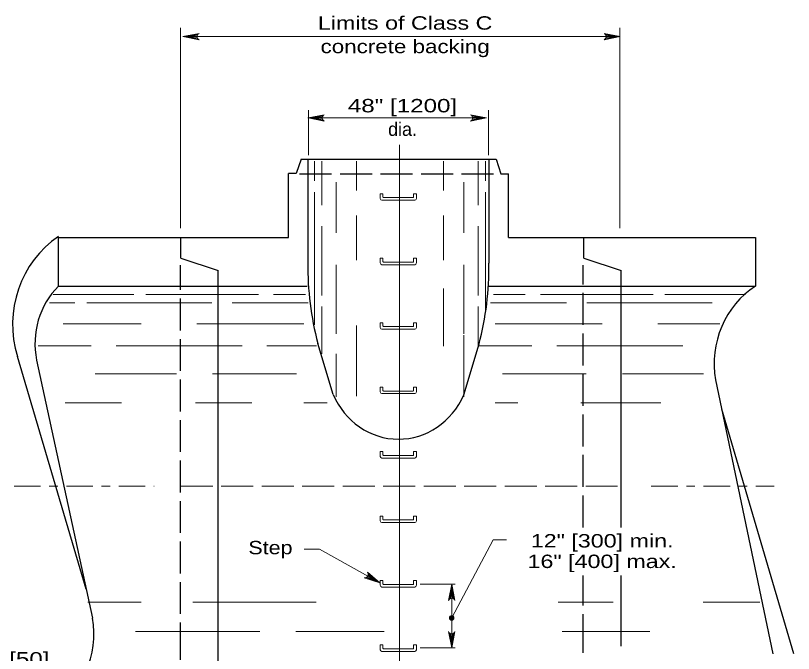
# Model space of a CAD drawing. Extents: x 1170.6 to 1204.6, y 975 to 1019.
# Drawn here: x 1175.39 to 1184.45, y 1000.96 to 1008.4 of the extents above; entities that cross this region are included whole.
import ezdxf
from ezdxf.enums import TextEntityAlignment as Align

# ---------------------------------------------------------------- set-up
doc = ezdxf.new("R2010")
doc.units = 0
doc.header["$LTSCALE"] = 0.062
doc.linetypes.add('DOT_DASHED', pattern=[7.7, 5, -1.2, 0.3, -1.2])
doc.linetypes.add('LONG_DASHED', pattern=[7.5, 6, -1.5])
doc.layers.add('1', color=7, linetype='Continuous', lineweight=13)

msp = doc.modelspace()

# ---------------------------------------------------------------- hatches: boundary and pattern name
at = {"layer": '1'}
msp.add_hatch(color=256, dxfattribs=at).paths.add_polyline_path([(1180.49779, 1001.37637, 1), (1180.44436, 1001.37637, 1)])

# ---------------------------------------------------------------- linework, layer by layer
for p, q in [((1177.30833, 1005.91808), (1177.30833, 1008.25417)), ((1177.50883, 1008.1745), (1177.33917, 1008.15075)), ((1182.26492, 1008.1745), (1182.43458, 1008.15075)), ((1182.43183, 1005.91808), (1182.43183, 1008.25417)), ((1177.50308, 1008.16275), (1177.33917, 1008.15075)), ((1177.33917, 1008.15075), (1182.43458, 1008.15075)), ((1177.50133, 1008.15075), (1177.33917, 1008.15075)), ((1177.50433, 1008.1355), (1177.33917, 1008.15075)), ((1177.51083, 1008.1245), (1177.33917, 1008.15075)), ((1182.26292, 1008.1245), (1182.43458, 1008.15075)), ((1182.26942, 1008.1355), (1182.43458, 1008.15075)), ((1182.27067, 1008.16275), (1182.43458, 1008.15075)), ((1182.27242, 1008.15075), (1182.43458, 1008.15075)), ((1178.80183, 1006.76825), (1178.80183, 1007.29333)), ((1180.89992, 1006.76825), (1180.89992, 1007.29333)), ((1180.89992, 1006.76825), (1180.89992, 1007.29333)), ((1178.79275, 1007.20317), (1180.878, 1007.20317)), ((1178.96883, 1007.22692), (1178.79917, 1007.20317)), ((1178.96308, 1007.21517), (1178.79917, 1007.20317)), ((1178.96133, 1007.20317), (1178.79917, 1007.20317)), ((1178.96433, 1007.188), (1178.79917, 1007.20317)), ((1178.97083, 1007.177), (1178.79917, 1007.20317)), ((1180.70633, 1007.177), (1180.878, 1007.20317)), ((1180.70833, 1007.22692), (1180.878, 1007.20317)), ((1180.71283, 1007.188), (1180.878, 1007.20317)), ((1180.71408, 1007.21517), (1180.878, 1007.20317)), ((1180.71583, 1007.20317), (1180.878, 1007.20317)), ((1179.86242, 1005.99008), (1179.86242, 1006.88858)), ((1178.87175, 1006.46967), (1178.87175, 1006.69792)), ((1178.95575, 1006.18633), (1178.95575, 1006.69792)), ((1179.36083, 1006.35633), (1179.36083, 1006.69792)), ((1180.37458, 1006.35633), (1180.37458, 1006.69792)), ((1180.77967, 1006.18633), (1180.77967, 1006.69792)), ((1180.86375, 1006.46967), (1180.86375, 1006.69792)), ((1179.12392, 1005.86258), (1179.12392, 1006.45342)), ((1180.6115, 1005.86258), (1180.6115, 1006.45342)), ((1178.87175, 1004.79408), (1178.87175, 1006.34017)), ((1179.63633, 1006.31975), (1179.63633, 1006.26408)), ((1179.63633, 1006.31975), (1179.67017, 1006.31975)), ((1179.63633, 1006.31975), (1179.63633, 1006.26408)), ((1179.63633, 1006.31975), (1179.67017, 1006.31975)), ((1179.67033, 1006.31975), (1179.67033, 1006.28108)), ((1179.67033, 1006.31975), (1179.67033, 1006.28108)), ((1179.84867, 1006.27467), (1179.67683, 1006.27467)), ((1179.84867, 1006.27467), (1179.67683, 1006.27467)), ((1179.84867, 1006.27467), (1180.0205, 1006.27467)), ((1179.84867, 1006.27467), (1180.0205, 1006.27467)), ((1180.027, 1006.31975), (1180.027, 1006.28108)), ((1180.027, 1006.31975), (1180.027, 1006.28108)), ((1180.06092, 1006.31975), (1180.02717, 1006.31975)), ((1180.06092, 1006.31975), (1180.02717, 1006.31975)), ((1180.06092, 1006.31975), (1180.06092, 1006.26408)), ((1180.06092, 1006.31975), (1180.06092, 1006.26408)), ((1180.86375, 1004.94383), (1180.86375, 1006.34017)), ((1179.84867, 1006.24375), (1179.65758, 1006.24375)), ((1179.84867, 1006.24375), (1179.65758, 1006.24375)), ((1179.84867, 1006.24375), (1180.03967, 1006.24375)), ((1179.84867, 1006.24375), (1180.03967, 1006.24375)), ((1179.36083, 1005.54683), (1179.36083, 1006.065)), ((1179.86242, 1000.46425), (1179.86242, 1006.03058)), ((1180.37458, 1005.54683), (1180.37458, 1006.065)), ((1181.13325, 1005.817), (1181.13325, 1006.03058)), ((1178.95575, 1005.134), (1178.95575, 1005.9435)), ((1180.77967, 1005.134), (1180.77967, 1005.9435)), ((1179.63633, 1005.5685), (1179.63633, 1005.51283)), ((1179.63633, 1005.5685), (1179.67017, 1005.5685)), ((1179.63633, 1005.5685), (1179.63633, 1005.51283)), ((1179.63633, 1005.5685), (1179.67017, 1005.5685)), ((1179.67033, 1005.5685), (1179.67033, 1005.52983)), ((1179.67033, 1005.5685), (1179.67033, 1005.52983)), ((1180.027, 1005.5685), (1180.027, 1005.52983)), ((1180.027, 1005.5685), (1180.027, 1005.52983)), ((1180.06092, 1005.5685), (1180.02717, 1005.5685)), ((1180.06092, 1005.5685), (1180.02717, 1005.5685)), ((1180.06092, 1005.5685), (1180.06092, 1005.51283)), ((1180.06092, 1005.5685), (1180.06092, 1005.51283)), ((1179.12392, 1004.68883), (1179.12392, 1005.49025)), ((1179.84867, 1005.4925), (1179.65758, 1005.4925)), ((1179.84867, 1005.4925), (1179.65758, 1005.4925)), ((1179.84867, 1005.52342), (1179.67683, 1005.52342)), ((1179.84867, 1005.52342), (1179.67683, 1005.52342)), ((1179.84867, 1005.52342), (1180.0205, 1005.52342)), ((1179.84867, 1005.52342), (1180.0205, 1005.52342)), ((1179.84867, 1005.4925), (1180.03967, 1005.4925)), ((1179.84867, 1005.4925), (1180.03967, 1005.4925)), ((1180.6115, 1004.68883), (1180.6115, 1005.49025)), ((1180.37458, 1004.54317), (1180.37458, 1005.21492)), ((1175.82733, 1005.14475), (1176.76683, 1005.14475)), ((1176.90442, 1005.14475), (1178.21883, 1005.14475)), ((1178.39467, 1005.14475), (1178.76525, 1005.14475)), ((1181.32925, 1005.14475), (1180.95867, 1005.14475)), ((1182.81958, 1005.14475), (1181.50508, 1005.14475)), ((1183.89658, 1005.14475), (1182.95717, 1005.14475)), ((1175.78142, 1005.04767), (1176.079, 1005.04767)), ((1176.2165, 1005.04767), (1177.67625, 1005.04767)), ((1177.91317, 1005.04767), (1178.79967, 1005.04767)), ((1178.95575, 1004.45408), (1178.95575, 1005.00458)), ((1180.77967, 1004.52692), (1180.77967, 1005.00458)), ((1181.81075, 1005.04767), (1180.92425, 1005.04767)), ((1183.50742, 1005.04767), (1182.04767, 1005.04767)), ((1179.63633, 1004.81725), (1179.63633, 1004.76158)), ((1179.63633, 1004.81725), (1179.67017, 1004.81725)), ((1179.63633, 1004.81725), (1179.63633, 1004.76158)), ((1179.63633, 1004.81725), (1179.67017, 1004.81725)), ((1179.67033, 1004.81725), (1179.67033, 1004.77858)), ((1179.67033, 1004.81725), (1179.67033, 1004.77858)), ((1180.027, 1004.81725), (1180.027, 1004.77858)), ((1180.027, 1004.81725), (1180.027, 1004.77858)), ((1180.06092, 1004.81725), (1180.02717, 1004.81725)), ((1180.06092, 1004.81725), (1180.02717, 1004.81725)), ((1180.06092, 1004.81725), (1180.06092, 1004.76158)), ((1180.06092, 1004.81725), (1180.06092, 1004.76158)), ((1175.94142, 1004.80483), (1176.85092, 1004.80483)), ((1177.50042, 1004.80483), (1178.74617, 1004.80483)), ((1179.36083, 1003.96033), (1179.36083, 1004.786)), ((1179.84867, 1004.74125), (1179.65758, 1004.74125)), ((1179.84867, 1004.74125), (1179.65758, 1004.74125)), ((1179.84867, 1004.77217), (1179.67683, 1004.77217)), ((1179.84867, 1004.77217), (1179.67683, 1004.77217)), ((1179.84867, 1004.77217), (1180.0205, 1004.77217)), ((1179.84867, 1004.77217), (1180.0205, 1004.77217)), ((1179.84867, 1004.74125), (1180.03967, 1004.74125)), ((1179.84867, 1004.74125), (1180.03967, 1004.74125)), ((1182.2235, 1004.80483), (1180.97783, 1004.80483)), ((1183.59525, 1004.80483), (1182.873, 1004.80483)), ((1180.6115, 1003.95225), (1180.6115, 1004.67267)), ((1175.6515, 1004.54592), (1176.27008, 1004.54592)), ((1176.5605, 1004.54592), (1178.02783, 1004.54592)), ((1178.31825, 1004.54592), (1178.897, 1004.54592)), ((1181.40575, 1004.54592), (1180.78667, 1004.54592)), ((1183.16342, 1004.54592), (1181.69617, 1004.54592)), ((1179.12392, 1003.95225), (1179.12392, 1004.45408)), ((1176.31592, 1004.222), (1177.26358, 1004.222)), ((1177.68392, 1004.222), (1178.66208, 1004.222)), ((1182.04, 1004.222), (1181.06183, 1004.222)), ((1183.40808, 1004.222), (1182.46033, 1004.222)), ((1179.63633, 1004.06608), (1179.63633, 1004.01033)), ((1179.63633, 1004.06608), (1179.67017, 1004.06608)), ((1179.63633, 1004.06608), (1179.63633, 1004.01033)), ((1179.63633, 1004.06608), (1179.67017, 1004.06608)), ((1179.67033, 1004.06608), (1179.67033, 1004.02733)), ((1179.67033, 1004.06608), (1179.67033, 1004.02733)), ((1179.84867, 1004.02092), (1179.67683, 1004.02092)), ((1179.84867, 1004.02092), (1179.67683, 1004.02092)), ((1179.84867, 1004.02092), (1180.0205, 1004.02092)), ((1179.84867, 1004.02092), (1180.0205, 1004.02092)), ((1180.027, 1004.06608), (1180.027, 1004.02733)), ((1180.027, 1004.06608), (1180.027, 1004.02733)), ((1180.06092, 1004.06608), (1180.02717, 1004.06608)), ((1180.06092, 1004.06608), (1180.02717, 1004.06608)), ((1180.06092, 1004.06608), (1180.06092, 1004.01033)), ((1180.06092, 1004.06608), (1180.06092, 1004.01033)), ((1179.84867, 1003.99), (1179.65758, 1003.99)), ((1179.84867, 1003.99), (1179.65758, 1003.99)), ((1179.84867, 1003.99), (1180.03967, 1003.99)), ((1179.84867, 1003.99), (1180.03967, 1003.99)), ((1175.96433, 1003.882), (1176.62167, 1003.882)), ((1177.48517, 1003.882), (1178.1425, 1003.882)), ((1178.74625, 1003.882), (1179.02133, 1003.882)), ((1180.97775, 1003.882), (1181.24325, 1003.882)), ((1182.90933, 1003.882), (1181.977, 1003.882)), ((1179.63633, 1003.31483), (1179.63633, 1003.25908)), ((1179.63633, 1003.31483), (1179.67017, 1003.31483)), ((1179.63633, 1003.31483), (1179.63633, 1003.25908)), ((1179.63633, 1003.31483), (1179.67017, 1003.31483)), ((1179.67033, 1003.31483), (1179.67033, 1003.27608)), ((1179.67033, 1003.31483), (1179.67033, 1003.27608)), ((1179.84867, 1003.26967), (1179.67683, 1003.26967)), ((1179.84867, 1003.26967), (1179.67683, 1003.26967)), ((1179.84867, 1003.26967), (1180.0205, 1003.26967)), ((1179.84867, 1003.26967), (1180.0205, 1003.26967)), ((1180.027, 1003.31483), (1180.027, 1003.27608)), ((1180.027, 1003.31483), (1180.027, 1003.27608)), ((1180.06092, 1003.31483), (1180.02717, 1003.31483)), ((1180.06092, 1003.31483), (1180.02717, 1003.31483)), ((1180.06092, 1003.31483), (1180.06092, 1003.25908)), ((1180.06092, 1003.31483), (1180.06092, 1003.25908)), ((1179.84867, 1003.23883), (1179.65758, 1003.23883)), ((1179.84867, 1003.23883), (1179.65758, 1003.23883)), ((1179.84867, 1003.23883), (1180.03967, 1003.23883)), ((1179.84867, 1003.23883), (1180.03967, 1003.23883)), ((1179.63633, 1002.56358), (1179.63633, 1002.50783)), ((1179.63633, 1002.56358), (1179.67017, 1002.56358)), ((1179.63633, 1002.56358), (1179.63633, 1002.50783)), ((1179.63633, 1002.56358), (1179.67017, 1002.56358)), ((1179.67033, 1002.56358), (1179.67033, 1002.52483)), ((1179.67033, 1002.56358), (1179.67033, 1002.52483)), ((1180.027, 1002.56358), (1180.027, 1002.52483)), ((1180.027, 1002.56358), (1180.027, 1002.52483)), ((1180.06092, 1002.56358), (1180.02717, 1002.56358)), ((1180.06092, 1002.56358), (1180.02717, 1002.56358)), ((1180.06092, 1002.56358), (1180.06092, 1002.50783)), ((1180.06092, 1002.56358), (1180.06092, 1002.50783)), ((1179.84867, 1002.48758), (1179.65758, 1002.48758)), ((1179.84867, 1002.48758), (1179.65758, 1002.48758)), ((1179.84867, 1002.51842), (1179.67683, 1002.51842)), ((1179.84867, 1002.51842), (1179.67683, 1002.51842)), ((1179.84867, 1002.51842), (1180.0205, 1002.51842)), ((1179.84867, 1002.51842), (1180.0205, 1002.51842)), ((1179.84867, 1002.48758), (1180.03967, 1002.48758)), ((1179.84867, 1002.48758), (1180.03967, 1002.48758)), ((1179.47408, 1001.84858), (1179.6335, 1001.78592)), ((1179.48483, 1001.856), (1179.6335, 1001.78592)), ((1179.49225, 1001.86558), (1179.6335, 1001.78592)), ((1179.49692, 1001.89308), (1179.6335, 1001.78592)), ((1179.49717, 1001.88033), (1179.6335, 1001.78592)), ((1179.63633, 1001.81233), (1179.63633, 1001.75658)), ((1179.63633, 1001.81233), (1179.67017, 1001.81233)), ((1179.63633, 1001.81233), (1179.63633, 1001.75658)), ((1179.63633, 1001.81233), (1179.67017, 1001.81233)), ((1179.84867, 1001.73633), (1179.65758, 1001.73633)), ((1179.84867, 1001.73633), (1179.65758, 1001.73633)), ((1179.67033, 1001.81233), (1179.67033, 1001.77358)), ((1179.67033, 1001.81233), (1179.67033, 1001.77358)), ((1179.84867, 1001.76717), (1179.67683, 1001.76717)), ((1179.84867, 1001.76717), (1179.67683, 1001.76717)), ((1179.84867, 1001.76717), (1180.0205, 1001.76717)), ((1179.84867, 1001.76717), (1180.0205, 1001.76717)), ((1179.84867, 1001.73633), (1180.03967, 1001.73633)), ((1179.84867, 1001.73633), (1180.03967, 1001.73633)), ((1180.027, 1001.81233), (1180.027, 1001.77358)), ((1180.027, 1001.81233), (1180.027, 1001.77358)), ((1180.06092, 1001.81233), (1180.02717, 1001.81233)), ((1180.06092, 1001.81233), (1180.02717, 1001.81233)), ((1180.06092, 1001.81233), (1180.06092, 1001.75658)), ((1180.06092, 1001.81233), (1180.06092, 1001.75658)), ((1180.10492, 1001.76967), (1180.51083, 1001.76967)), ((1180.44483, 1001.59658), (1180.47108, 1001.76825)), ((1180.45583, 1001.60308), (1180.47108, 1001.76825)), ((1180.47108, 1001.029), (1180.47108, 1001.76825)), ((1180.47108, 1001.029), (1180.47108, 1001.76825)), ((1180.47108, 1001.60608), (1180.47108, 1001.76825)), ((1180.48308, 1001.60433), (1180.47108, 1001.76825)), ((1180.49483, 1001.59858), (1180.47108, 1001.76825)), ((1176.85158, 1001.56), (1176.23158, 1001.56)), ((1178.89183, 1001.56), (1177.45225, 1001.56)), ((1182.35258, 1001.56), (1181.71383, 1001.56)), ((1184.06458, 1001.56), (1183.40133, 1001.56)), ((1176.78483, 1001.21992), (1178.234, 1001.21992)), ((1178.65342, 1001.21992), (1179.68317, 1001.21992)), ((1180.44733, 1001.19858), (1180.47108, 1001.029)), ((1180.45908, 1001.19283), (1180.47108, 1001.029)), ((1180.49733, 1001.20058), (1180.47108, 1001.029)), ((1180.48633, 1001.19408), (1180.47108, 1001.029)), ((1180.47108, 1001.19117), (1180.47108, 1001.029)), ((1181.757, 1001.21992), (1182.78158, 1001.21992)), ((1179.63633, 1001.06108), (1179.63633, 1001.00533)), ((1179.63633, 1001.06108), (1179.67017, 1001.06108)), ((1179.63633, 1001.06108), (1179.63633, 1001.00533)), ((1179.63633, 1001.06108), (1179.67017, 1001.06108)), ((1179.67033, 1001.06108), (1179.67033, 1001.02233)), ((1179.67033, 1001.06108), (1179.67033, 1001.02233)), ((1179.84867, 1001.01592), (1179.67683, 1001.01592)), ((1179.84867, 1001.01592), (1179.67683, 1001.01592)), ((1179.84867, 1001.01592), (1180.0205, 1001.01592)), ((1179.84867, 1001.01592), (1180.0205, 1001.01592)), ((1180.027, 1001.06108), (1180.027, 1001.02233)), ((1180.027, 1001.06108), (1180.027, 1001.02233)), ((1180.06092, 1001.06108), (1180.02717, 1001.06108)), ((1180.06092, 1001.06108), (1180.02717, 1001.06108)), ((1180.06092, 1001.06108), (1180.06092, 1001.00533)), ((1180.06092, 1001.06108), (1180.06092, 1001.00533)), ((1180.10275, 1001.02683), (1180.51083, 1001.02683)), ((1179.84867, 1000.98508), (1179.65758, 1000.98508)), ((1179.84867, 1000.98508), (1179.65758, 1000.98508)), ((1179.84867, 1000.98508), (1180.03967, 1000.98508)), ((1179.84867, 1000.98508), (1180.03967, 1000.98508))]:
    msp.add_line(p, q, dxfattribs=at)
at = {"layer": '1', "lineweight": 25}
for p, q in [((1178.71667, 1006.7225), (1178.65942, 1006.5545)), ((1178.79575, 1006.71942), (1178.79575, 1006.01433)), ((1180.90442, 1006.71942), (1180.90442, 1005.96583)), ((1178.65958, 1006.55425), (1178.57008, 1006.55425)), ((1178.57008, 1005.80992), (1178.57008, 1006.55425)), ((1181.04267, 1006.55333), (1181.13325, 1006.55333)), ((1181.13325, 1005.80992), (1181.13325, 1006.55333)), ((1178.57008, 1005.81792), (1178.57008, 1006.03058)), ((1178.79575, 1006.03058), (1178.79575, 1005.51475)), ((1180.90442, 1006.03058), (1180.90442, 1005.509)), ((1175.88767, 1005.24283), (1175.88767, 1005.80992)), ((1175.88767, 1005.80992), (1178.57008, 1005.80992)), ((1181.13325, 1005.80992), (1184.01167, 1005.80992)), ((1184.01167, 1005.80992), (1184.01167, 1005.24283)), ((1177.3145, 1005.57092), (1177.3145, 1005.8045)), ((1182.00983, 1005.57092), (1182.00983, 1005.8045)), ((1177.3145, 1005.57092), (1177.75008, 1005.42475)), ((1182.00983, 1005.57092), (1182.44542, 1005.42475)), ((1182.44542, 1002.43117), (1182.44542, 1005.42475)), ((1175.88767, 1005.24283), (1178.78625, 1005.24283)), ((1180.8935, 1005.24283), (1184.01167, 1005.24283)), ((1179.08892, 1003.98075), (1178.91033, 1004.5745)), ((1180.61125, 1003.97508), (1180.78983, 1004.56883)), ((1176.2115, 1001.7115), (1175.40958, 1004.42192)), ((1175.6325, 1004.38142), (1176.2845, 1001.37525)), ((1183.545, 1004.14933), (1184.21617, 1000.9575)), ((1183.61792, 1003.81308), (1184.45458, 1000.9625)), ((1182.44542, 1001.04808), (1182.44542, 1001.87108))]:
    msp.add_line(p, q, dxfattribs=at)
at = {"layer": '1', "linetype": 'LONG_DASHED', "lineweight": 25}
for p, q in [((1178.69883, 1006.55358), (1181.00992, 1006.55358)), ((1182.004, 1002.43117), (1182.004, 1005.486)), ((1182.004, 1001.04808), (1182.004, 1001.87108)), ((1182.004, 1000.96917), (1182.004, 1001.04808))]:
    msp.add_line(p, q, dxfattribs=at)
at = {"layer": '1', "linetype": 'DOT_DASHED'}
for p, q in [((1174.75975, 1002.91058), (1177.00483, 1002.91058)), ((1182.79675, 1002.91058), (1184.23067, 1002.91058))]:
    msp.add_line(p, q, dxfattribs=at)
at = {"layer": '1', "linetype": 'LONG_DASHED'}
msp.add_line((1177.31367, 1002.91058), (1182.42, 1002.91058), dxfattribs=at)
at = {"layer": '1'}
for points in [[(1177.52658, 1008.11325), (1177.33917, 1008.15075), (1177.52658, 1008.18825)], [(1182.24717, 1008.11325), (1182.43458, 1008.15075), (1182.24717, 1008.18825)], [(1178.98658, 1007.16575), (1178.79917, 1007.20317), (1178.98658, 1007.24067)], [(1180.69058, 1007.16575), (1180.878, 1007.20317), (1180.69058, 1007.24067)], [(1181.11058, 1002.28567), (1180.95542, 1002.28567), (1180.47108, 1001.37633)], [(1179.6335, 1001.78592), (1178.93092, 1002.17842), (1178.7525, 1002.17842)], [(1179.48867, 1001.91058), (1179.6335, 1001.78592), (1179.45192, 1001.84533)], [(1180.43358, 1001.58083), (1180.47108, 1001.76825), (1180.50858, 1001.58083)], [(1180.50858, 1001.21633), (1180.47108, 1001.029), (1180.43358, 1001.21633)]]:
    msp.add_lwpolyline(points, dxfattribs=at)
at = {"layer": '1', "lineweight": 25}
for points in [[(1178.71667, 1006.7225), (1180.98933, 1006.7225), (1181.04267, 1006.55333)], [(1177.75008, 1000.081), (1177.75008, 1000.951), (1177.75008, 1005.42475)]]:
    msp.add_lwpolyline(points, dxfattribs=at)
at = {"layer": '1', "linetype": 'LONG_DASHED', "lineweight": 25}
msp.add_lwpolyline([(1177.30867, 999.94333), (1177.30867, 1000.951), (1177.30867, 1005.486)], dxfattribs=at)
at = {"layer": '1'}
msp.add_circle((1180.47107, 1001.37637), 0.02671, dxfattribs=at)
for centre, start, end in [((1177.54173, 1008.15078), 112.08782, 247.91395), ((1182.23202, 1008.15078), 292.08605, 67.91218), ((1179.00171, 1007.20324), 112.08782, 247.91395), ((1180.67544, 1007.20324), 292.08605, 67.91218), ((1179.45708, 1001.88536), 262.67925, 38.50537), ((1180.47112, 1001.5657), 22.08782, 157.91395), ((1180.47103, 1001.2315), 202.08782, 337.91395)]:
    msp.add_arc(centre, 0.04045, start, end, dxfattribs=at)
for centre, major_axis, start_param, end_param in [((1179.6581, 1006.26695), (0, -0.0232), 4.8374934, 6.2601456), ((1179.6581, 1006.26695), (0, -0.0232), 4.8374934, 6.2601456), ((1179.67645, 1006.2811), (0, -0.00648), 4.7166392, 6.345136), ((1179.67645, 1006.2811), (0, -0.00648), 4.7166392, 6.345136), ((1180.02084, 1006.2811), (0, -0.00648), 6.2212346, 7.8497314), ((1180.02084, 1006.2811), (0, -0.00648), 6.2212346, 7.8497314), ((1180.0392, 1006.26695), (0, -0.0232), 0.0230398, 1.4456919), ((1180.0392, 1006.26695), (0, -0.0232), 0.0230398, 1.4456919), ((1179.6581, 1005.5157), (0, -0.0232), 4.8374934, 6.2601456), ((1179.6581, 1005.5157), (0, -0.0232), 4.8374934, 6.2601456), ((1179.67645, 1005.52985), (0, -0.00648), 4.7166392, 6.345136), ((1179.67645, 1005.52985), (0, -0.00648), 4.7166392, 6.345136), ((1180.02084, 1005.52985), (0, -0.00648), 6.2212346, 7.8497314), ((1180.02084, 1005.52985), (0, -0.00648), 6.2212346, 7.8497314), ((1180.0392, 1005.5157), (0, -0.0232), 0.0230398, 1.4456919), ((1180.0392, 1005.5157), (0, -0.0232), 0.0230398, 1.4456919), ((1179.6581, 1004.76446), (0, -0.0232), 4.8374934, 6.2601456), ((1179.6581, 1004.76446), (0, -0.0232), 4.8374934, 6.2601456), ((1179.67645, 1004.77861), (0, -0.00648), 4.7166392, 6.345136), ((1179.67645, 1004.77861), (0, -0.00648), 4.7166392, 6.345136), ((1180.02084, 1004.77861), (0, -0.00648), 6.2212346, 7.8497314), ((1180.02084, 1004.77861), (0, -0.00648), 6.2212346, 7.8497314), ((1180.0392, 1004.76446), (0, -0.0232), 0.0230398, 1.4456919), ((1180.0392, 1004.76446), (0, -0.0232), 0.0230398, 1.4456919), ((1179.6581, 1004.01321), (0, -0.0232), 4.8374934, 6.2601456), ((1179.6581, 1004.01321), (0, -0.0232), 4.8374934, 6.2601456), ((1179.67645, 1004.02736), (0, -0.00648), 4.7166392, 6.345136), ((1179.67645, 1004.02736), (0, -0.00648), 4.7166392, 6.345136), ((1180.02084, 1004.02736), (0, -0.00648), 6.2212346, 7.8497314), ((1180.02084, 1004.02736), (0, -0.00648), 6.2212346, 7.8497314), ((1180.0392, 1004.01321), (0, -0.0232), 0.0230398, 1.4456919), ((1180.0392, 1004.01321), (0, -0.0232), 0.0230398, 1.4456919), ((1179.67645, 1003.27612), (0, -0.00648), 4.7166392, 6.345136), ((1179.67645, 1003.27612), (0, -0.00648), 4.7166392, 6.345136), ((1180.02084, 1003.27612), (0, -0.00648), 6.2212346, 7.8497314), ((1180.02084, 1003.27612), (0, -0.00648), 6.2212346, 7.8497314), ((1179.6581, 1003.26197), (0, -0.0232), 4.8374934, 6.2601456), ((1179.6581, 1003.26197), (0, -0.0232), 4.8374934, 6.2601456), ((1180.0392, 1003.26197), (0, -0.0232), 0.0230398, 1.4456919), ((1180.0392, 1003.26197), (0, -0.0232), 0.0230398, 1.4456919), ((1179.6581, 1002.51072), (0, -0.0232), 4.8374934, 6.2601456), ((1179.6581, 1002.51072), (0, -0.0232), 4.8374934, 6.2601456), ((1179.67645, 1002.52487), (0, -0.00648), 4.7166392, 6.345136), ((1179.67645, 1002.52487), (0, -0.00648), 4.7166392, 6.345136), ((1180.02084, 1002.52487), (0, -0.00648), 6.2212346, 7.8497314), ((1180.02084, 1002.52487), (0, -0.00648), 6.2212346, 7.8497314), ((1180.0392, 1002.51072), (0, -0.0232), 0.0230398, 1.4456919), ((1180.0392, 1002.51072), (0, -0.0232), 0.0230398, 1.4456919), ((1179.6581, 1001.75948), (0, -0.0232), 4.8374934, 6.2601456), ((1179.6581, 1001.75948), (0, -0.0232), 4.8374934, 6.2601456), ((1179.67645, 1001.77363), (0, -0.00648), 4.7166392, 6.345136), ((1179.67645, 1001.77363), (0, -0.00648), 4.7166392, 6.345136), ((1180.02084, 1001.77363), (0, -0.00648), 6.2212346, 7.8497314), ((1180.02084, 1001.77363), (0, -0.00648), 6.2212346, 7.8497314), ((1180.0392, 1001.75948), (0, -0.0232), 0.0230398, 1.4456919), ((1180.0392, 1001.75948), (0, -0.0232), 0.0230398, 1.4456919), ((1179.6581, 1001.00824), (0, -0.0232), 4.8374934, 6.2601456), ((1179.6581, 1001.00824), (0, -0.0232), 4.8374934, 6.2601456), ((1179.67645, 1001.02239), (0, -0.00648), 4.7166392, 6.345136), ((1179.67645, 1001.02239), (0, -0.00648), 4.7166392, 6.345136), ((1180.02084, 1001.02239), (0, -0.00648), 6.2212346, 7.8497314), ((1180.02084, 1001.02239), (0, -0.00648), 6.2212346, 7.8497314), ((1180.0392, 1001.00824), (0, -0.0232), 0.0230398, 1.4456919), ((1180.0392, 1001.00824), (0, -0.0232), 0.0230398, 1.4456919)]:
    msp.add_ellipse(centre, major_axis=major_axis, ratio=0.944544, start_param=start_param, end_param=end_param, dxfattribs=at)
at = {"layer": '1', "lineweight": 25}
for centre, major_axis, start_param, end_param in [((1176.49284, 1004.79789), (0, 1.20684), 0.5596414, 1.8877058), ((1181.88907, 1005.4593), (0, 3.27539), 1.5538687, 1.8443113), ((1177.81114, 1005.45357), (0, 3.27539), 4.438874, 4.7293166), ((1176.47915, 1004.57329), (0, 0.91671), 0.7519933, 1.7816017), ((1184.53221, 1004.33542), (0, 1.06162), 0.5457717, 1.7469569), ((1179.85135, 1004.34512), (0, -0.88558), 5.1363708, 7.4228635), ((1175.29726, 1001.18918), (0, -1.06162), 0.5457717, 1.7469569)]:
    msp.add_ellipse(centre, major_axis=major_axis, ratio=0.944544, start_param=start_param, end_param=end_param, dxfattribs=at)

# ---------------------------------------------------------------- texts
at = {"layer": '1'}
for s, width, p in [('Limits of Class C', 1.3, (1179.92825, 1008.23217)), ('concrete backing', 1.25, (1179.92825, 1007.95817)), ('48" [1200]', 1.35, (1179.89792, 1007.2685)), ('12" [300] min.', 1.3, (1182.22487, 1002.19717)), ('16" [400] max.', 1.3, (1182.22483, 1001.95792)), ('2" [50]', 1.35, (1175.38071, 1000.82133))]:
    msp.add_text(s, height=0.156, dxfattribs=dict(at, width=width)).set_placement(p, align=Align.CENTER)
msp.add_text('dia.', height=0.156, dxfattribs=at).set_placement((1179.89796, 1006.9945), align=Align.CENTER)
at = {"layer": '1', "width": 1.2}
msp.add_text('Step', height=0.156, dxfattribs=at).set_placement((1178.10092, 1002.11808))

doc.saveas('drawing.dxf')
